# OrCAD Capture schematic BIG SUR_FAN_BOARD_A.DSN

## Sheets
1 01 Cover page: title: Big Sur; rev: A; company: Quanta
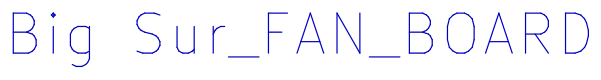
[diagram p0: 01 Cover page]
2 02 FAN CONN: size Custom
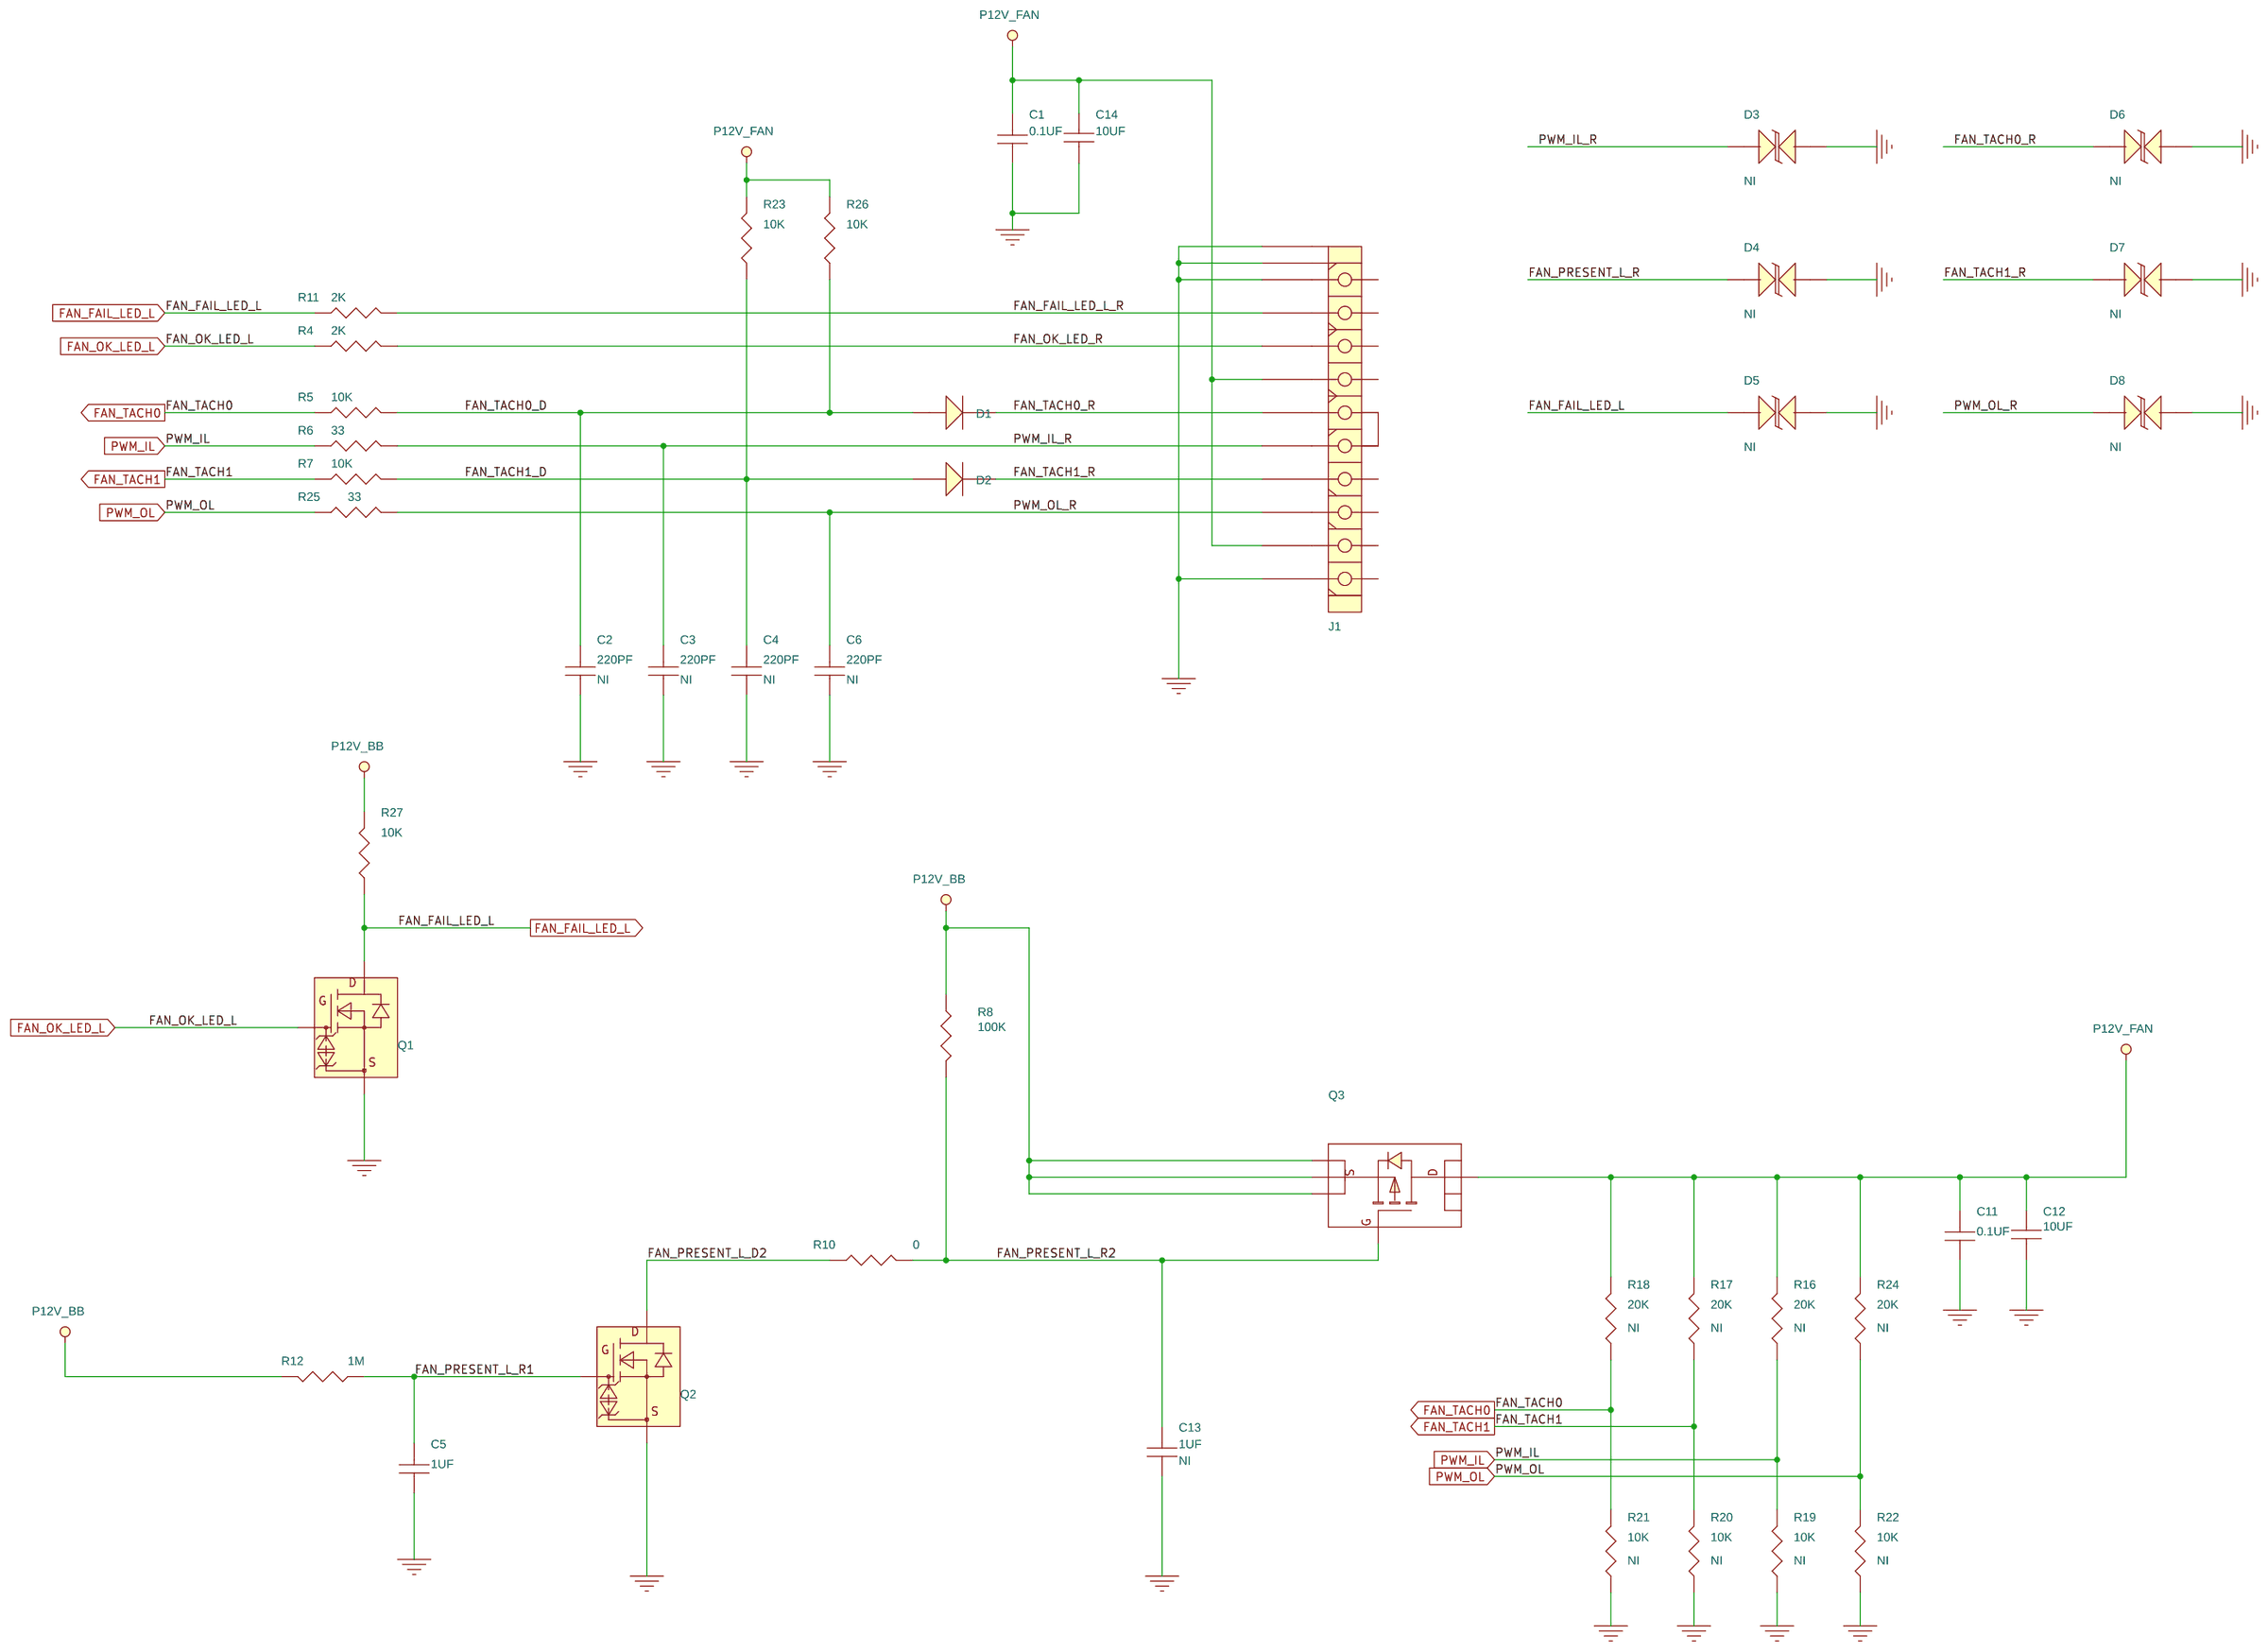
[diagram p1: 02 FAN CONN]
3 03 FAN PCIe CONN: size B
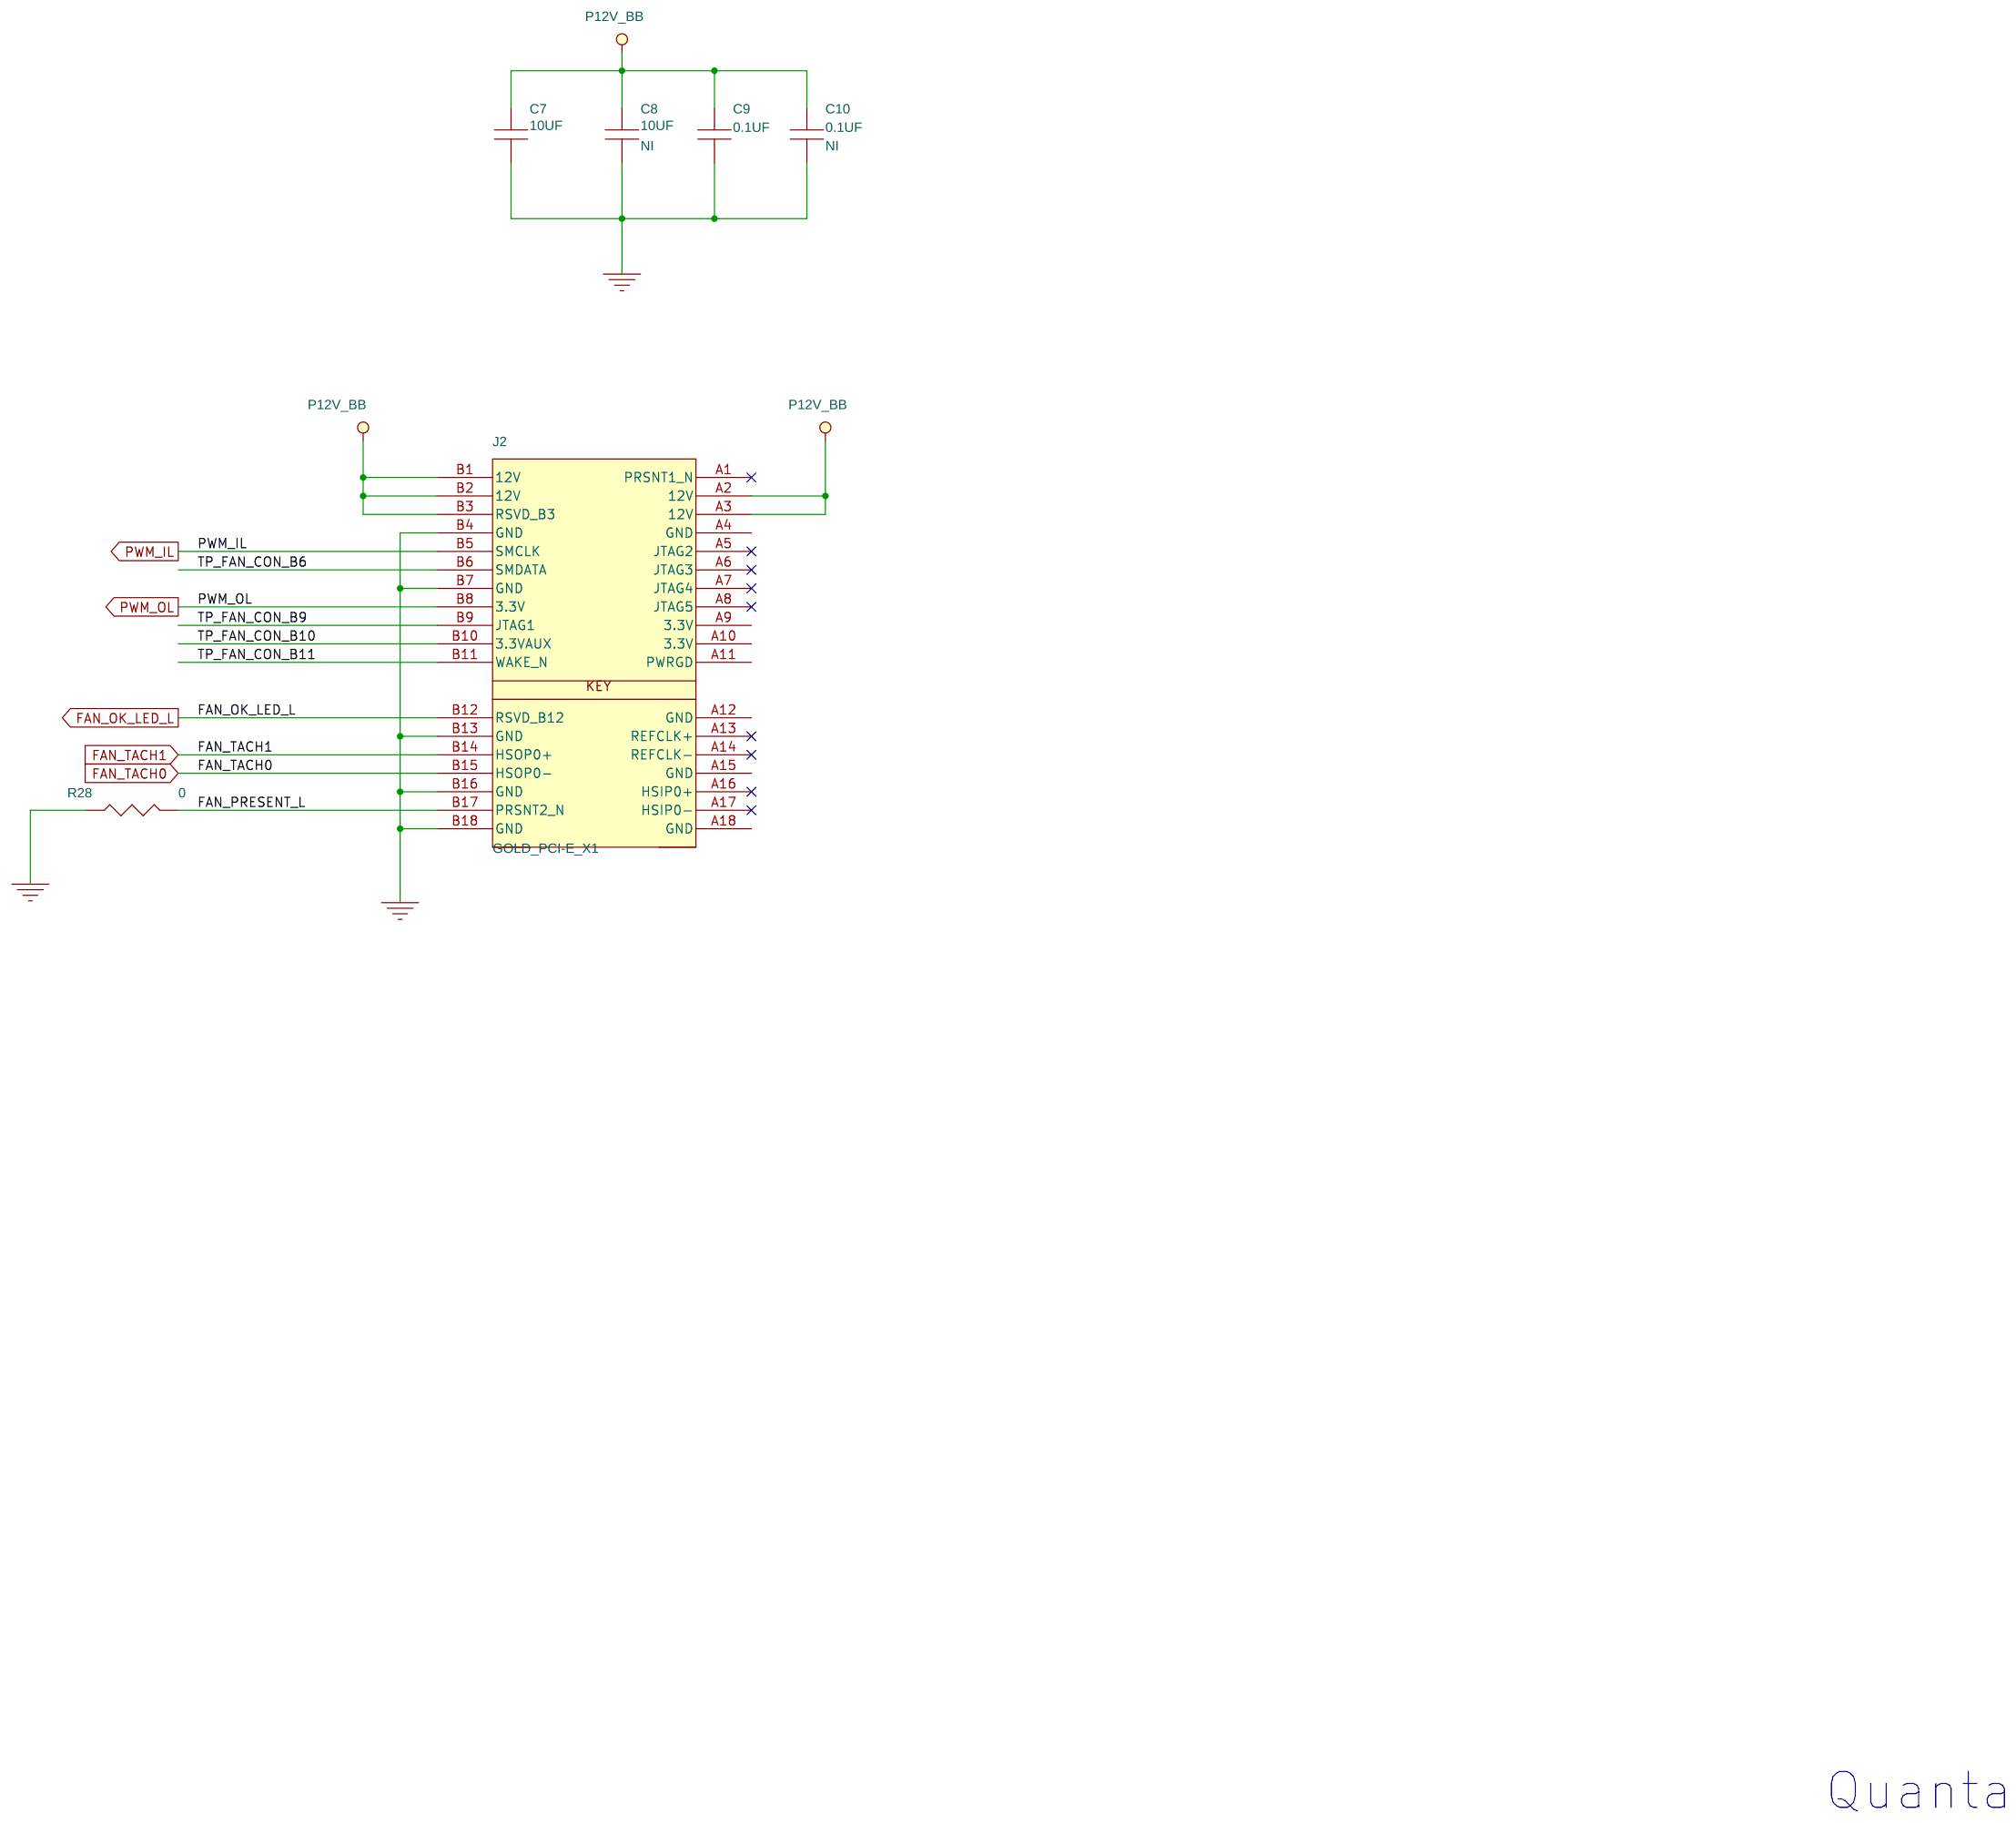
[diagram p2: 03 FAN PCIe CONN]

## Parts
sheet 02 FAN CONN
C1  0.1UF  [C0402]
C2  220PF  [C0402]
C3  220PF  [C0402]
C4  220PF  [C0402]
C5  1UF  [C0603]
C6  220PF  [C0402]
C11  0.1UF  [C0402]
C12  10UF  [C1206_H76]
C13  1UF  [C0402]
C14  10UF  [C1206_H76]
D1  SDMK0340L-7-F  [SOD323]
D2  SDMK0340L-7-F  [SOD323]
D3  UCLAMP0511T  [SLP1006P2T]
D4  UCLAMP0511T  [SLP1006P2T]
D5  UCLAMP0511T  [SLP1006P2T]
D6  UCLAMP0511T  [SLP1006P2T]
D7  UCLAMP0511T  [SLP1006P2T]
D8  UCLAMP0511T  [SLP1006P2T]
J1  436501014  [CON_PWR1X10SHR]
Q1  2N7002K  [SOT23_GDSXC]
Q2  2N7002K  [SOT23_GDSXC]
Q3  AP6681GMT-HF  [PMPAK5]
R4  2K  [R0402]
R5  10K  [R0402]
R6  33  [R0402]
R7  10K  [R0402]
R8  100K  [R0402]
R10  0  [R0402]
R11  2K  [R0402]
R12  1M  [R0603]
R16  20K  [R0402]
R17  20K  [R0402]
R18  20K  [R0402]
R19  10K  [R0402]
R20  10K  [R0402]
R21  10K  [R0402]
R22  10K  [R0402]
R23  10K  [R0402]
R24  20K  [R0402]
R25  33  [R0402]
R26  10K  [R0402]
R27  10K  [R0603]
sheet 03 FAN PCIe CONN
C7  10UF  [C1206_H76]
C8  10UF  [C1206_H76]
C9  0.1UF  [C0402]
C10  0.1UF  [C0402]
J2  GOLD_PCI-E_X1  [GOLD_PCI-E_X1]
R28  0  [R0402]

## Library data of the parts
C1 C9 C11 = CAP_NP: Part_Type: *LF_C0402
C2-C4 C6 C10 C13 = CAP_NP: Not_insert: NI; Part_Type: *LF_C0402
C5 = CAP_NP: Part_Type: *LF_C0603
C7 C12 C14 = CAP_NP: Part_Type: *LF_C1206
D1 D2 = DIODE: Part_Type: *LF_Semiconductor
D3-D8 = DIODE_BIDIRECTIONAL: Not_insert: NI; Part_Type: *LF_Semiconductor
J1 = 436501012
Q1 Q2 = MOSFET_NCH_GDS_ESD_PROTECTED: Part_Type: *LF_Semiconductor
Q3 = MOSFET_PCH_1D3S: Part_Type: *LF_Semiconductor
R4-R8 R10 R11 R23 R25 R26 R28 = R: Part_Type: *LF_Resistor; WATTAGE: 1/16W
R12 R27 = R: Part_Type: *LF_Resistor; WATTAGE: 1/10W
R16-R22 R24 = R: Not_insert: NI; Part_Type: *LF_Resistor; WATTAGE: 1/16W
C8 = CAP_NP: Not_insert: NI; Part_Type: *LF_C1206
J2 = PCI_EXPRESS_X1_CONN_1: Part_Type: Misc

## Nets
3.3V: J2.A9(3.3V) J2.A10(3.3V)
GND: C1.1 C2.1 C3.1 C4.1 C5.1 C6.1 C7.2 C8.2 C9.2 C10.2 C11.1 C12.2 C13.1 C14.2 D3.A D4.A D5.A D6.A D7.A D8.A J1.1 J1.10 J1.G1 J1.G2 J2.A4(GND) J2.A12(GND) J2.A15(GND) J2.A18(GND) J2.B4(GND) J2.B7(GND) J2.B13(GND) J2.B16(GND) J2.B18(GND) Q1.S Q2.S R19.1 R20.1 R21.1 R22.1 R28.1
P12V_BB: C7.1 C8.1 C9.1 C10.1 J2.A2(12V) J2.A3(12V) J2.B1(12V) J2.B2(12V) J2.B3(RSVD) Q3.1 Q3.2 Q3.3 R8.1 R12.2 R27.2
P12V_FAN: C1.2 C11.2 C12.1 C14.1 J1.2 J1.7 Q3.5 R16.2 R17.2 R18.2 R23.2 R24.2 R26.2
FAN_FAIL_LED_L: D5.C Q1.D R11.2 R27.1
FAN_FAIL_LED_L_R: J1.9 R11.1
FAN_OK_LED_L: J2.B12(RSVD) Q1.G R4.2
FAN_OK_LED_R: J1.8 R4.1
FAN_PRESENT_L: J2.B17(PRSNT2_N) R28.2
FAN_PRESENT_L_D2: Q2.D R10.1
FAN_PRESENT_L_R: D4.C
FAN_PRESENT_L_R1: C5.2 Q2.G R12.1
FAN_PRESENT_L_R2: C13.2 Q3.4 R8.2 R10.2
FAN_TACH0: J2.B15(HSOP0-) R5.2 R18.1 R21.2
FAN_TACH0_D: C2.2 D1.1 R5.1 R26.1
FAN_TACH0_R: D1.2 D6.C J1.6
FAN_TACH1: J2.B14(HSOP0+) R7.2 R17.1 R20.2
FAN_TACH1_D: C4.2 D2.1 R7.1 R23.1
FAN_TACH1_R: D2.2 D7.C J1.4
PWM_IL: J2.B5(SMCLK) R6.1 R16.1 R19.2
PWM_IL_R: C3.2 D3.C J1.5 R6.2
PWM_OL: J2.B8(3.3V) R22.2 R24.1 R25.1
PWM_OL_R: C6.2 D8.C J1.3 R25.2
PWRGD: J2.A11(PWRGD)
TP_FAN_CON_B6: J2.B6(SMDATA)
TP_FAN_CON_B9: J2.B9(JTAG1)
TP_FAN_CON_B10: J2.B10(3.3VAUX)
TP_FAN_CON_B11: J2.B11(WAKE_N)

Not connected (* = marked no-connect by the designer): J2 A1(PRSNT1_N)* A5(JTAG2)* A6(JTAG3)* A7(JTAG4)* A8(JTAG5)* A13(REFCLK+)* A14(REFCLK-)* A16(HSIP0+)* A17(HSIP0-)*

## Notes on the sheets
sheet 1
- Big Sur_FAN_BOARD
sheet 3
- Quanta
